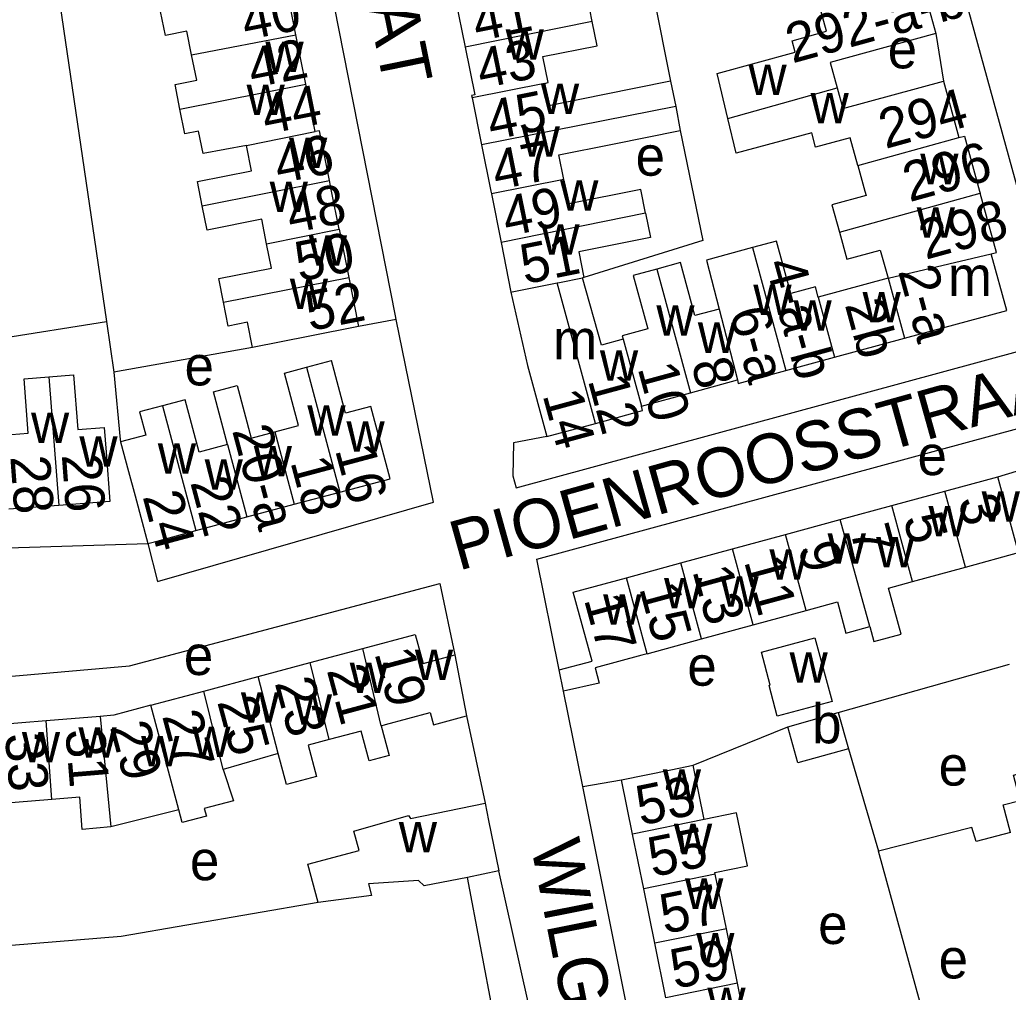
# Model space of a CAD drawing. Extents: x 161258 to 163262, y 380749 to 382054.
# Drawn here: x 162485.9 to 162585.9, y 380919 to 381017.4 of the extents above; entities that cross this region are included whole.
import ezdxf

# ---------------------------------------------------------------- set-up
doc = ezdxf.new("R2010")
doc.units = 0
for name, color, linetype in [('BLT_Basislijn', 7, 'Continuous'), ('BLT_Bebouwing', 7, 'Continuous'), ('BLT_Centroide', 7, 'Continuous'), ('BLT_Huisnummer', 7, 'Continuous'), ('BLT_Huisnummer_ tussenligend', 7, 'Continuous'), ('BLT_Huisnummer_reeks', 7, 'Continuous'), ('BLT_Onderverdeling_panden', 7, 'Continuous'), ('BLT_Straatnaam', 7, 'Continuous')]:
    doc.layers.add(name, color=color, linetype=linetype)

msp = doc.modelspace()

# ---------------------------------------------------------------- linework, layer by layer
at = {"layer": 'BLT_Basislijn'}
for p, q in [((162533.059, 381104.233), (162551.715, 381011.13)), ((162564.459, 381081.624), (162588.618, 380993.566)), ((162578.526, 381015.953), (162579.314, 381011.149)), ((162480.039, 380984.524), (162494.651, 380986.823)), ((162494.651, 380986.823), (162495.404, 380981.701)), ((162523.964, 380987.032), (162520.131, 380986.332)), ((162509.432, 380984.21), (162495.404, 380981.701)), ((162568.66, 380947.267), (162585.983, 380952.176)), ((162531.067, 380946.918), (162532.941, 380938.103)), ((162553.978, 380941.942), (162563.562, 380945.828)), ((162569.69, 380943.611), (162572.74, 380933.251)), ((162542.823, 380939.778), (162546.739, 380940.463)), ((162556.162, 380873.404), (162542.823, 380939.778)), ((162534.009, 380915.533), (162531.157, 380930.593))]:
    msp.add_line(p, q, dxfattribs=at)
for points in [[(162523.964, 380987.032), (162523.887, 380987.412), (162498.765, 381114.822)], [(162476.763, 381110.89), (162482.455, 381069.727), (162494.651, 380986.823)], [(162552.689, 381006.158), (162554.96, 380995.035), (162542.944, 380991.274)], [(162498.83, 380964.374), (162499.812, 380960.513), (162527.73, 380968.544), (162523.964, 380987.032)], [(162539.181, 380975.181), (162535.808, 380974.554), (162535.739, 380971.213), (162536.085, 380970.016), (162591.008, 380984.952)], [(162468.171, 380983.192), (162470.472, 380963.496), (162498.83, 380964.374)], [(162495.404, 380981.701), (162496.021, 380974.883), (162496.082, 380974.654)], [(162540.442, 380951.594), (162538.172, 380962.773), (162593.02, 380977.699)], [(162476.974, 380950.245), (162496.975, 380951.991), (162528.362, 380960.33), (162529.874, 380953.09)], [(162542.823, 380939.778), (162540.886, 380949.419)], [(162586.107, 380935.141), (162582.607, 380934.211), (162582.174, 380935.638), (162572.74, 380933.251)], [(162534.846, 380908.256), (162538.821, 380909.253), (162538.713, 380911.611), (162534.342, 380931.244)], [(162516.071, 380928.041), (162496.149, 380924.609), (162485.055, 380923.703)]]:
    msp.add_lwpolyline(points, dxfattribs=at)
at = {"layer": 'BLT_Bebouwing'}
for p, q in [((162576.886, 381021.944), (162578.526, 381015.953)), ((162513.812, 381015.826), (162512.834, 381020.734)), ((162529.951, 381019.403), (162530.923, 381014.582)), ((162514.805, 381010.848), (162513.812, 381015.826)), ((162551.715, 381011.13), (162552.232, 381008.563)), ((162579.314, 381011.149), (162580.879, 381005.431)), ((162515.763, 381006.041), (162514.805, 381010.848)), ((162531.623, 381009.439), (162532.581, 381004.69)), ((162552.232, 381008.563), (162552.689, 381006.158)), ((162533.58, 380999.728), (162534.558, 380994.83)), ((162518.182, 380996.156), (162519.149, 380991.282)), ((162534.558, 380994.83), (162535.537, 380989.794)), ((162519.149, 380991.282), (162520.131, 380986.332)), ((162542.944, 380991.274), (162542.814, 380991.248)), ((162568.3, 380983.203), (162575.368, 380985.129)), ((162563.381, 380981.862), (162568.3, 380983.203)), ((162514.872, 380982.207), (162517.404, 380982.883)), ((162553.721, 380979.621), (162558.464, 380980.913)), ((162548.757, 380978.267), (162553.721, 380979.621)), ((162539.181, 380975.181), (162544.105, 380976.523)), ((162579.441, 380969.668), (162584.804, 380971.127)), ((162513.634, 380968.331), (162518.253, 380969.565)), ((162574.074, 380968.207), (162579.441, 380969.668)), ((162489.816, 380968.225), (162484.785, 380967.842)), ((162508.85, 380967.052), (162513.634, 380968.331)), ((162568.845, 380966.785), (162574.074, 380968.207)), ((162503.674, 380965.669), (162508.85, 380967.052)), ((162563.339, 380965.287), (162568.845, 380966.785)), ((162557.972, 380963.826), (162563.339, 380965.287)), ((162552.735, 380962.401), (162557.972, 380963.826)), ((162581.532, 380961.982), (162586.895, 380963.441)), ((162547.238, 380960.906), (162552.735, 380962.401)), ((162576.165, 380960.521), (162581.532, 380961.982)), ((162560.063, 380956.14), (162565.431, 380957.601)), ((162549.329, 380953.22), (162554.85, 380954.722)), ((162515.265, 380952.325), (162520.566, 380953.749)), ((162510.004, 380950.913), (162515.265, 380952.325)), ((162504.51, 380949.437), (162510.004, 380950.913)), ((162499.145, 380947.996), (162504.51, 380949.437)), ((162563.562, 380945.828), (162568.66, 380947.267)), ((162568.66, 380947.267), (162569.69, 380943.611)), ((162488.56, 380946.423), (162483.053, 380945.969)), ((162494.022, 380946.872), (162488.56, 380946.423)), ((162512.005, 380943.12), (162506.45, 380941.511)), ((162555.104, 380936.43), (162553.978, 380941.942)), ((162547.865, 380934.952), (162546.739, 380940.463)), ((162489.131, 380938.485), (162483.722, 380938.039)), ((162548.991, 380929.437), (162547.865, 380934.952)), ((162577.91, 380914.476), (162572.74, 380933.251)), ((162534.342, 380931.244), (162531.157, 380930.593)), ((162557.356, 380925.401), (162556.23, 380930.916)), ((162550.117, 380923.922), (162548.991, 380929.437)), ((162558.483, 380919.886), (162557.356, 380925.401)), ((162551.244, 380918.407), (162550.117, 380923.922)), ((162559.609, 380914.371), (162558.483, 380919.886))]:
    msp.add_line(p, q, dxfattribs=at)
for points in [[(162543.784, 381017.175), (162543.29, 381019.625), (162537.813, 381018.522), (162537.346, 381020.838)], [(162557.513, 381007.372), (162556.428, 381011.914), (162564.322, 381014.072), (162564.004, 381015.234), (162567.473, 381016.183), (162566.662, 381019.148)], [(162503.262, 381013.812), (162502.784, 381016.206), (162500.608, 381015.773), (162500.124, 381018.2)], [(162538.949, 381010.917), (162539.328, 381010.994), (162538.799, 381013.62), (162544.278, 381014.725), (162543.784, 381017.175)], [(162578.526, 381015.953), (162567.858, 381013.032), (162568.561, 381010.465)], [(162530.923, 381014.582), (162531.896, 381009.754), (162531.573, 381009.689), (162531.623, 381009.439)], [(162502.086, 381008.314), (162501.588, 381010.812), (162503.773, 381011.248), (162503.262, 381013.812)], [(162551.715, 381011.13), (162544.841, 381009.745), (162539.406, 381008.65), (162538.949, 381010.917)], [(162568.561, 381010.465), (162569.137, 381008.362), (162579.314, 381011.149)], [(162508.802, 381004.631), (162504.423, 381003.817), (162503.97, 381006.093), (162502.584, 381005.817), (162502.086, 381008.314)], [(162570.654, 381002.611), (162569.887, 381005.416), (162566.381, 381004.457), (162565.979, 381005.926), (162558.357, 381003.841), (162557.513, 381007.372)], [(162517.201, 381001.094), (162516.198, 381006.128), (162515.763, 381006.041)], [(162540.907, 381001.206), (162540.408, 381003.683), (162545.842, 381004.778), (162552.689, 381006.158)], [(162580.879, 381005.431), (162581.427, 381005.581), (162582.955, 381000), (162583.011, 380999.798)], [(162504.34, 380998.539), (162503.852, 381000.996), (162509.309, 381002.083), (162508.802, 381004.631)], [(162532.581, 381004.69), (162533.526, 380999.999), (162533.58, 380999.728)], [(162570.654, 381002.611), (162571.369, 380999.998), (162571.483, 380999.587), (162568.029, 380998.635), (162568.79, 380995.876)], [(162518.182, 380996.156), (162517.417, 381000.013), (162517.201, 381001.094)], [(162549.164, 380997.798), (162548.687, 381000.183), (162541.407, 380998.729), (162540.907, 381001.206)], [(162584.129, 380993.669), (162584.66, 380993.815), (162583.011, 380999.798)], [(162510.85, 380994.701), (162510.358, 380997.18), (162504.828, 380996.083), (162504.34, 380998.539)], [(162549.164, 380997.798), (162549.66, 380995.314), (162542.426, 380993.869), (162542.944, 380991.274)], [(162568.79, 380995.876), (162569.55, 380993.118), (162572.924, 380994.049), (162573.702, 380991.217)], [(162506.477, 380988.767), (162506.002, 380991.163), (162511.341, 380992.223), (162510.85, 380994.701)], [(162559.988, 380994.309), (162555.347, 380993.043), (162556.621, 380988.088)], [(162566.641, 380989.293), (162566.354, 380990.346), (162563.855, 380989.665), (162562.41, 380994.969), (162559.988, 380994.309)], [(162575.368, 380985.129), (162585.707, 380987.946), (162584.129, 380993.669)], [(162550.313, 380992.13), (162547.922, 380991.479), (162549.392, 380986.082), (162546.818, 380985.381), (162546.915, 380985.027)], [(162556.621, 380988.088), (162554.166, 380987.419), (162552.705, 380992.782), (162550.313, 380992.13)], [(162546.915, 380985.027), (162544.712, 380984.427), (162542.814, 380991.248)], [(162573.702, 380991.217), (162566.641, 380989.293)], [(162535.537, 380989.794), (162537.223, 380982.367), (162539.181, 380975.181)], [(162509.432, 380984.21), (162508.926, 380986.762), (162506.953, 380986.371), (162506.477, 380988.767)], [(162520.131, 380986.332), (162515.227, 380985.359), (162509.432, 380984.21)], [(162511.677, 380975.649), (162514.072, 380976.29), (162512.649, 380981.613), (162514.872, 380982.207)], [(162521.395, 380978.223), (162518.833, 380977.539), (162517.404, 380982.883)], [(162484.216, 380975.328), (162486.742, 380975.52), (162486.322, 380981.042), (162488.826, 380981.232)], [(162488.826, 380981.232), (162491.33, 380981.423), (162491.75, 380975.909), (162494.429, 380976.113), (162494.62, 380973.605), (162494.999, 380968.619), (162489.816, 380968.225)], [(162558.464, 380980.913), (162558.558, 380980.548), (162563.381, 380981.862)], [(162506.895, 380974.377), (162505.472, 380979.701), (162507.858, 380980.339), (162509.282, 380975.009), (162511.677, 380975.649)], [(162500.302, 380978.302), (162498.004, 380977.688), (162498.633, 380975.335), (162496.082, 380974.654)], [(162506.895, 380974.377), (162504.019, 380973.608), (162502.6, 380978.916), (162500.302, 380978.302)], [(162518.253, 380969.565), (162523.345, 380970.926), (162521.395, 380978.223)], [(162544.105, 380976.523), (162548.878, 380977.824), (162548.757, 380978.267)], [(162496.082, 380974.654), (162496.881, 380971.664)], [(162584.804, 380971.127), (162589.703, 380972.58), (162590.612, 380972.813), (162592.725, 380965.028)], [(162496.881, 380971.664), (162497.539, 380969.205), (162498.83, 380964.374)], [(162498.83, 380964.374), (162500.003, 380964.688), (162503.674, 380965.669)], [(162540.442, 380951.594), (162543.774, 380952.449), (162541.87, 380959.445), (162547.238, 380960.906)], [(162571.864, 380955.959), (162572.278, 380954.465), (162575.022, 380955.211), (162573.756, 380959.865), (162576.165, 380960.521)], [(162565.431, 380957.601), (162568.582, 380958.458), (162569.441, 380955.299), (162571.864, 380955.959)], [(162554.85, 380954.722), (162560.063, 380956.14)], [(162520.566, 380953.749), (162525.886, 380955.178), (162526.677, 380952.231), (162529.874, 380953.09)], [(162529.874, 380953.09), (162531.067, 380946.918)], [(162549.329, 380953.22), (162548.787, 380953.072), (162544.078, 380951.791), (162544.483, 380950.243), (162540.886, 380949.419)], [(162540.886, 380949.419), (162540.442, 380951.594)], [(162499.145, 380947.996), (162495.39, 380946.985), (162494.022, 380946.872)], [(162522.426, 380945.934), (162522.888, 380946.058), (162527.397, 380947.269), (162527.733, 380946.022)], [(162527.733, 380946.022), (162531.067, 380946.918)], [(162522.426, 380945.934), (162523.234, 380942.925), (162521.219, 380942.384), (162520.411, 380945.393), (162517.177, 380944.524)], [(162569.69, 380943.611), (162564.59, 380942.176), (162563.562, 380945.828)], [(162517.177, 380944.524), (162515.034, 380943.949), (162515.878, 380940.806), (162512.845, 380939.991), (162512.005, 380943.12)], [(162506.45, 380941.511), (162507.496, 380938.348), (162504.546, 380937.556), (162504.752, 380936.787), (162502.316, 380936.133), (162501.969, 380937.434)], [(162546.739, 380940.463), (162551.723, 380941.481), (162553.978, 380941.942)], [(162586.107, 380935.141), (162585.363, 380937.921), (162587.084, 380938.381), (162586.402, 380940.929), (162588.872, 380941.59)], [(162495.078, 380935.687), (162492.207, 380935.45), (162491.938, 380938.717), (162489.131, 380938.485)], [(162516.071, 380928.041), (162515.022, 380931.931), (162520.22, 380933.293), (162519.676, 380935.261), (162525.185, 380936.859), (162525.408, 380936.563), (162532.941, 380938.103)], [(162532.941, 380938.103), (162533.298, 380936.353), (162534.342, 380931.244)], [(162501.969, 380937.434), (162495.078, 380935.687)], [(162556.23, 380930.916), (162556.193, 380931.097), (162559.478, 380931.768), (162558.384, 380937.121), (162555.104, 380936.43)], [(162531.157, 380930.593), (162526.8, 380929.72), (162526.226, 380930.269), (162521.145, 380929.952), (162521.472, 380928.769), (162516.071, 380928.041)]]:
    msp.add_lwpolyline(points, dxfattribs=at)
msp.add_lwpolyline([(162560.9, 380953.362), (162566.288, 380954.828), (162568.043, 380948.378), (162562.483, 380946.894), (162561.668, 380950.015), (162561.784, 380950.046)], close=True, dxfattribs=at)
at = {"layer": 'BLT_Onderverdeling_panden'}
for p, q in [((162543.784, 381017.175), (162530.923, 381014.582)), ((162503.262, 381013.812), (162513.812, 381015.826)), ((162502.086, 381008.314), (162514.805, 381010.848)), ((162538.949, 381010.917), (162531.623, 381009.439)), ((162557.513, 381007.372), (162568.561, 381010.465)), ((162552.232, 381008.563), (162532.581, 381004.69)), ((162508.802, 381004.631), (162515.763, 381006.041)), ((162570.654, 381002.611), (162580.879, 381005.431)), ((162504.34, 380998.539), (162517.201, 381001.094)), ((162540.907, 381001.206), (162533.58, 380999.728)), ((162568.79, 380995.876), (162583.011, 380999.798)), ((162549.164, 380997.798), (162534.558, 380994.83)), ((162510.85, 380994.701), (162518.182, 380996.156)), ((162559.988, 380994.309), (162563.381, 380981.862)), ((162573.702, 380991.217), (162584.129, 380993.669)), ((162550.313, 380992.13), (162553.721, 380979.621)), ((162506.477, 380988.767), (162519.149, 380991.282)), ((162573.702, 380991.217), (162575.368, 380985.129)), ((162544.105, 380976.523), (162540.234, 380990.733)), ((162566.641, 380989.293), (162568.3, 380983.203)), ((162556.621, 380988.088), (162558.464, 380980.913)), ((162546.915, 380985.027), (162548.757, 380978.267)), ((162514.872, 380982.207), (162518.253, 380969.565)), ((162488.826, 380981.232), (162489.816, 380968.225)), ((162500.302, 380978.302), (162503.674, 380965.669)), ((162511.677, 380975.649), (162513.634, 380968.331)), ((162506.895, 380974.377), (162508.85, 380967.052)), ((162586.895, 380963.441), (162584.804, 380971.127)), ((162581.532, 380961.982), (162579.441, 380969.668)), ((162576.165, 380960.521), (162574.074, 380968.207)), ((162571.864, 380955.959), (162568.845, 380966.785)), ((162565.431, 380957.601), (162563.339, 380965.287)), ((162560.063, 380956.14), (162557.972, 380963.826)), ((162554.85, 380954.722), (162552.735, 380962.401)), ((162549.329, 380953.22), (162547.238, 380960.906)), ((162522.426, 380945.934), (162520.566, 380953.749)), ((162517.177, 380944.524), (162515.265, 380952.325)), ((162512.005, 380943.12), (162510.004, 380950.913)), ((162506.45, 380941.511), (162504.51, 380949.437)), ((162501.969, 380937.434), (162499.145, 380947.996)), ((162489.131, 380938.485), (162488.56, 380946.423)), ((162494.022, 380946.872), (162495.078, 380935.687)), ((162555.104, 380936.43), (162547.865, 380934.952)), ((162556.23, 380930.916), (162548.991, 380929.437)), ((162557.356, 380925.401), (162550.117, 380923.922)), ((162558.483, 380919.886), (162551.244, 380918.407))]:
    msp.add_line(p, q, dxfattribs=at)
for points in [[(162540.234, 380990.733), (162540.466, 380990.779), (162542.814, 380991.248)], [(162535.537, 380989.794), (162535.698, 380989.827), (162540.234, 380990.733)]]:
    msp.add_lwpolyline(points, dxfattribs=at)

# ---------------------------------------------------------------- texts
at = {"layer": 'BLT_Centroide'}
for s, p in [('w', (162535.023, 381013.312)), ('w', (162510.727, 381012.062)), ('e', (162573.675, 381012.437)), ('w', (162559.587, 381009.755)), ('w', (162508.82, 381007.719)), ('w', (162538.594, 381007.812)), ('w', (162565.867, 381006.875)), ('w', (162536.641, 381003.5)), ('w', (162513.109, 381002.344)), ('e', (162548.172, 381001.577)), ('w', (162576.961, 381000.719)), ('w', (162540.539, 380998.031)), ('w', (162511.156, 380997.906)), ('w', (162576.602, 380995.312)), ('w', (162538.641, 380993.594)), ('w', (162515.109, 380992.469)), ('m', (162579.758, 380989.406)), ('w', (162513.195, 380988.094)), ('w', (162560.078, 380987.469)), ('w', (162571.125, 380986.75)), ('w', (162550.266, 380985.406)), ('w', (162564.141, 380985.906)), ('m', (162539.828, 380983)), ('w', (162554.469, 380983.656)), ('e', (162502.547, 380980.362)), ('w', (162544.562, 380980.828)), ('w', (162514.969, 380975.266)), ('w', (162487.016, 380974.547)), ('w', (162518.922, 380973.656)), ('w', (162491.906, 380972.141)), ('w', (162499.844, 380971.422)), ('w', (162509.547, 380971.172)), ('e', (162576.687, 380971.284)), ('w', (162504.578, 380969.828)), ('w', (162583.172, 380966.562)), ('w', (162577.797, 380965.094)), ('w', (162567.594, 380962.312)), ('w', (162572.5, 380961.953)), ('w', (162561.703, 380960.719)), ('w', (162556.75, 380957.984)), ('w', (162551.047, 380957.812)), ('w', (162544.891, 380956.141)), ('e', (162502.474, 380951.062)), ('w', (162525.844, 380950.562)), ('e', (162553.403, 380949.982)), ('w', (162563.739, 380950.293)), ('w', (162519.25, 380949.25)), ('w', (162508.25, 380946.234)), ('w', (162513.594, 380946.031)), ('b', (162566.025, 380944.152)), ('w', (162486.094, 380942.234)), ('w', (162491.812, 380942.703)), ('w', (162503.328, 380942.766)), ('w', (162498.156, 380941.828)), ('e', (162578.822, 380939.878)), ('w', (162550.922, 380938.438)), ('w', (162524.218, 380933.123)), ('w', (162552.047, 380932.938)), ('e', (162503.093, 380930.304)), ('w', (162553.172, 380927.406)), ('e', (162566.635, 380923.851)), ('w', (162554.305, 380921.906)), ('e', (162578.822, 380920.365)), ('w', (162555.43, 380916.375))]:
    msp.add_text(s, height=4, dxfattribs=at).set_placement(p)
at = {"layer": 'BLT_Huisnummer'}
for s, height, rotation, p in [('41', 4, 11.40616, (162532.119, 381015.152)), ('42', 3.9999, 11.26748, (162509.415, 381010.435)), ('45', 4, 11.40616, (162533.589, 381005.148)), ('294', 4, 15.41726, (162573.435, 381004.273)), ('46', 4, 11.23623, (162512.068, 381000.762)), ('298', 4, 15.24309, (162577.5, 380993.064)), ('51', 4, 11.28971, (162536.94, 380990.591)), ('52', 4, 11.22228, (162515.211, 380985.848)), ('2b', 3.9999, 285.23901, (162569.318, 380988.546)), ('8', 4, 285.24, (162553.761, 380982.602)), ('14', 3.9999, 285.24162, (162538.741, 380979.397)), ('16', 4, 284.97186, (162517.746, 380973.853)), ('26', 4, 274.34661, (162490.122, 380973.342)), ('24', 4, 284.96168, (162498.287, 380969.14)), ('5', 4, 285.21977, (162575.209, 380966.916)), ('9', 4, 285.22294, (162564.578, 380964.02)), ('13', 3.9999, 285.22105, (162553.897, 380961.597)), ('17', 4, 285.2261, (162542.931, 380958.721)), ('19', 4, 285.03483, (162521.732, 380953.281)), ('23', 4, 285.03483, (162511.645, 380950.283)), ('27', 4, 285.03668, (162500.257, 380946.934)), ('31', 4, 274.71401, (162490.482, 380945.495)), ('53', 4, 11.53958, (162548.659, 380935.824)), ('57', 4, 11.54563, (162551.079, 380924.853))]:
    msp.add_text(s, height=height, rotation=rotation, dxfattribs=at).set_placement(p)
at = {"layer": 'BLT_Huisnummer_ tussenligend'}
for s, height, rotation, p in [('40', 4, 11.26729, (162508.741, 381015.268)), ('43', 4, 11.40616, (162532.546, 381010.372)), ('44', 3.9999, 11.26748, (162510.791, 381005.74)), ('47', 4, 11.40616, (162534.095, 381000.107)), ('296', 4, 15.41726, (162575.867, 380998.889)), ('48', 4, 11.23623, (162513.291, 380995.725)), ('49', 4, 11.40616, (162535.145, 380995.418)), ('50', 4, 11.23623, (162514.151, 380990.859)), ('10', 3.9999, 285.24, (162548.352, 380982.123)), ('12', 3.9999, 285.24, (162543.321, 380980.893)), ('28', 4, 274.34661, (162484.915, 380973.16)), ('18', 4, 284.97186, (162513.234, 380972.629)), ('22', 4, 284.94497, (162503.104, 380970.565)), ('3', 4, 285.21977, (162580.743, 380968.771)), ('7', 4, 285.21977, (162569.825, 380965.713)), ('11', 4, 285.22294, (162559.117, 380962.574)), ('15', 3.9999, 285.22105, (162548.515, 380959.86)), ('21', 4, 285.03483, (162516.916, 380951.556)), ('25', 4, 285.03483, (162505.83, 380948.365)), ('29', 4, 285.03668, (162494.976, 380945.824)), ('33', 4, 274.71401, (162484.369, 380945.076)), ('55', 4, 11.53958, (162549.874, 380930.613)), ('59', 4, 11.54563, (162552.129, 380919.295))]:
    msp.add_text(s, height=height, rotation=rotation, dxfattribs=at).set_placement(p)
at = {"layer": 'BLT_Huisnummer_reeks'}
for s, height, rotation, p in [('292-a-b', 4, 15.41857, (162564.027, 381012.927)), ('4-a-b', 3.9999, 285.24084, (162561.259, 380992.702)), ('2-a', 3.9999, 285.23901, (162574.708, 380991.936)), ('6-a', 3.9999, 285.24084, (162557.633, 380987.779)), ('20-a', 4, 284.94497, (162507.339, 380975.816))]:
    msp.add_text(s, height=height, rotation=rotation, dxfattribs=at).set_placement(p)
at = {"layer": 'BLT_Straatnaam'}
for s, height, rotation, p in [('WILGENROOSSTRAAT', 5, 281.53414, (162508.279, 381081.382)), ('PIOENROOSSTRAAT', 5, 15.60128, (162530.246, 380961.592)), ('WILGENROOSSTRAAT', 4.99999, 281.21389, (162537.546, 380933.871))]:
    msp.add_text(s, height=height, rotation=rotation, dxfattribs=at).set_placement(p)

doc.saveas('drawing.dxf')
